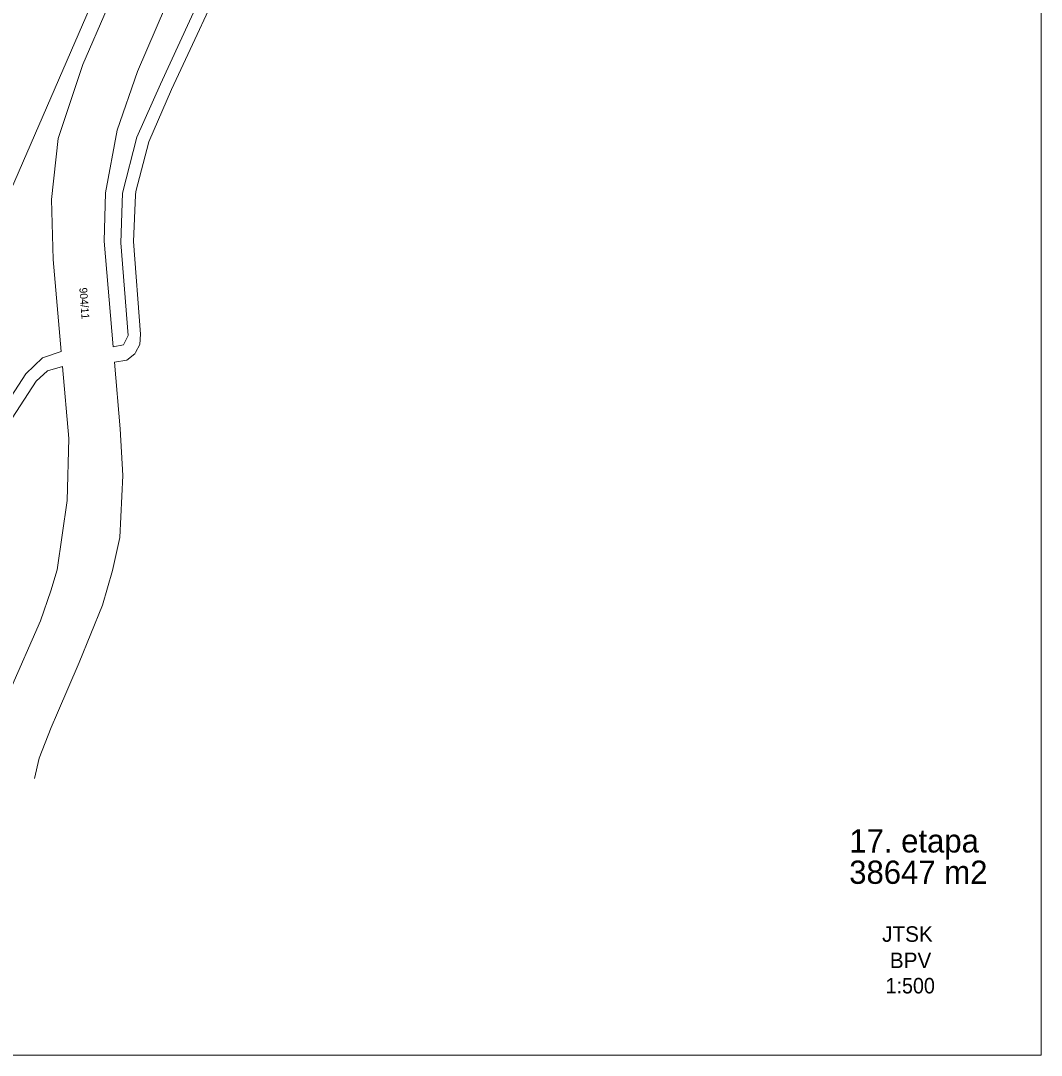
# Model space of a CAD drawing. Extents: x -843400 to -842830, y -1002860 to -1002082.
# Drawn here: x -842961.8 to -842830.1, y -1002860 to -1002726.5 of the extents above; entities that cross this region are included whole.
import ezdxf
from ezdxf.enums import TextEntityAlignment as Align

# ---------------------------------------------------------------- set-up
doc = ezdxf.new("R2010")
doc.units = 0
doc.header["$LTSCALE"] = 0.4
for name, color, linetype, lineweight in [('32', 7, 'Continuous', 13), ('34', 7, 'Continuous', 13), ('43', 7, 'Continuous', 13), ('44', 7, 'Continuous', 13)]:
    doc.layers.add(name, color=color, linetype=linetype, lineweight=lineweight)

msp = doc.modelspace()

# ---------------------------------------------------------------- linework, layer by layer
at = {"layer": '32'}
for points in [[(-842949.73, -1002770.53), (-842948.12, -1002770.28), (-842947.09, -1002769.45), (-842946.99, -1002769.3), (-842946.43, -1002768.26), (-842946.36, -1002766.94), (-842947.25, -1002754.97), (-842947.02, -1002748.98), (-842946.95, -1002748.51), (-842945.3, -1002742.1), (-842942.37, -1002735.33), (-842934.56, -1002718.61), (-842926.46, -1002700.13), (-842920.81, -1002683.35), (-842919.88, -1002680.59), (-842915.57, -1002667.81), (-842928.42, -1002663.65), (-842931.89, -1002663.34)], [(-842960.06, -1002824.29), (-842959.45, -1002821.63), (-842957.91, -1002817.71), (-842957.07, -1002815.79), (-842954.27, -1002809.28), (-842951.28, -1002801.9), (-842949.96, -1002797.41), (-842949.03, -1002793.19), (-842948.64, -1002785.16), (-842948.97, -1002779.16), (-842949.73, -1002770.53)]]:
    msp.add_lwpolyline(points, dxfattribs=at)
at = {"layer": '43'}
for points in [[(-842948.56, -1002768.3), (-842947.94, -1002767.12), (-842948.92, -1002755.12), (-842948.68, -1002748.71), (-842946.84, -1002741.5), (-842943.78, -1002734.66), (-842936.02, -1002717.81), (-842928, -1002699.57), (-842922.39, -1002682.86), (-842917.91, -1002669.43), (-842917.91, -1002668.95), (-842918.75, -1002668.47), (-842929.16, -1002665.07), (-842931.62, -1002665.4), (-842933.52, -1002666.36), (-842929.19, -1002681.38), (-842929.83, -1002691.39), (-842931.73, -1002698.15), (-842939.66, -1002716.51), (-842946.75, -1002733.04), (-842949.38, -1002740.61), (-842950.88, -1002748.67), (-842951.06, -1002754.94), (-842949.88, -1002768.58)], [(-842963.26, -1002813.05), (-842959.28, -1002803.94), (-842957.93, -1002800.07), (-842957.1, -1002797.33), (-842955.81, -1002788.38), (-842955.61, -1002780.41), (-842956.41, -1002771.1), (-842958.35, -1002771.68), (-842959.84, -1002773), (-842977.33, -1002799.92), (-842969.68, -1002809.15), (-842967.9, -1002810.77), (-842966.14, -1002811.8)]]:
    msp.add_lwpolyline(points, close=True, dxfattribs=at)
msp.add_lwpolyline([(-842940.49, -1002696.12), (-842968.25, -1002760.14), (-843000.72, -1002744.8), (-843010.07, -1002772.62), (-843014.071, -1002784.19), (-842983.31, -1002792.93), (-842982.45, -1002793.71), (-842978.37, -1002798.58), (-842961.17, -1002772.04), (-842959.01, -1002769.99), (-842956.6, -1002769.16), (-842957.64, -1002757.28), (-842957.86, -1002749.53), (-842956.98, -1002741.66), (-842953.8, -1002732.13), (-842944.4, -1002710.39)], dxfattribs=at)
at = {"layer": '44'}
msp.add_lwpolyline([(-842830.097, -1002859.997), (-842830.097, -1002081.989), (-843400.094, -1002081.989), (-843400.094, -1002859.997)], close=True, dxfattribs=at)

# ---------------------------------------------------------------- texts
at = {"layer": '34'}
msp.add_text('904/11', height=1, rotation=274.281, dxfattribs=at).set_placement((-842954.1082, -1002762.9877), align=Align.CENTER)
at = {"layer": '44'}
for s, height, p in [('17. etapa', 3, (-842854.881, -1002833.825)), ('38647 m2', 3, (-842854.89, -1002837.868)), ('JTSK', 2, (-842850.645, -1002845.349)), ('BPV', 2, (-842849.648, -1002848.744))]:
    msp.add_text(s, height=height, dxfattribs=at).set_placement(p)
at = {"layer": '44', "width": 0.95}
msp.add_text('1:500', height=2, dxfattribs=at).set_placement((-842850.195, -1002852.009))

doc.saveas('drawing.dxf')
